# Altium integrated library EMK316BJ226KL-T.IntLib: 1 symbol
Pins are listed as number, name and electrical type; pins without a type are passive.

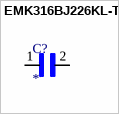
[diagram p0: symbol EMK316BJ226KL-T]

## EMK316BJ226KL-T
designator C?
Cap Ceramic 22uF 16V X5R 10% Pad SMD 1206 85C T/R; MP: EMK316BJ226KL-T
footprint CAPC3216X180N
pins: 1, 2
